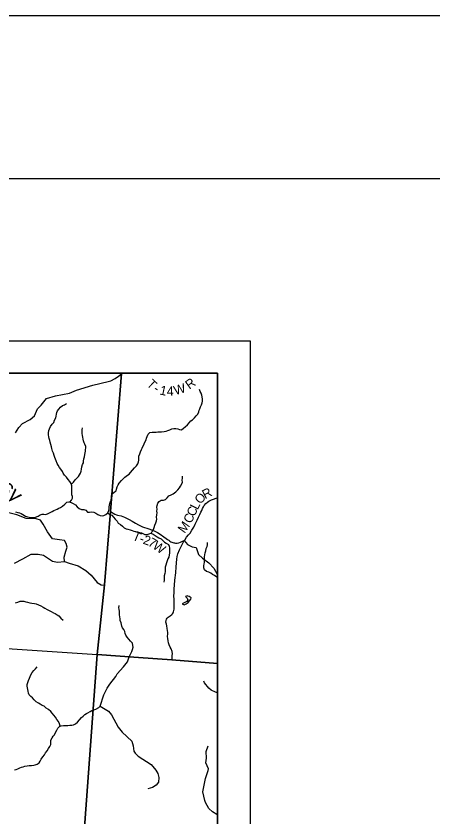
# Model space of a CAD drawing. Extents: x 0 to 42, y 0 to 22.
# Drawn here: x 8.279 to 9.563, y 19.536 to 22 of the extents above; entities that cross this region are included whole.
import ezdxf

# ---------------------------------------------------------------- set-up
doc = ezdxf.new("R2010")
doc.units = 0
for name, color, linetype in [('GM_X_Minor_Lake', 7, 'Continuous'), ('GM_X_Minor_River', 7, 'Continuous'), ('GM_X_Minor_River_Text', 7, 'Continuous'), ('GM_X_Township', 7, 'Continuous'), ('GM_X_Township_Road', 7, 'Continuous'), ('GM_X_Township_Road_Text', 7, 'Continuous'), ('SH_Border', 7, 'Continuous'), ('SH_Cut_Line', 7, 'Continuous'), ('SH_Data', 7, 'Continuous')]:
    doc.layers.add(name, color=color, linetype=linetype)

msp = doc.modelspace()

# ---------------------------------------------------------------- linework, layer by layer
at = {"layer": 'GM_X_Minor_Lake'}
for points in [[(8.8084, 20.2136), (8.8065, 20.2141), (8.8011, 20.2124), (8.8066, 20.2069), (8.8086, 20.202), (8.8047, 20.1969), (8.7905, 20.19)], [(8.7905, 20.19), (8.7969, 20.1862), (8.8034, 20.1893), (8.8098, 20.1942), (8.8138, 20.199), (8.8172, 20.2037), (8.8183, 20.2085), (8.8128, 20.2124), (8.8084, 20.2136)]]:
    msp.add_lwpolyline(points, dxfattribs=at)
at = {"layer": 'GM_X_Minor_River'}
for points in [[(8.5716, 20.5078), (8.5723, 20.5094), (8.5731, 20.5162), (8.5736, 20.521), (8.5747, 20.5274), (8.581, 20.5337), (8.5876, 20.5382), (8.5887, 20.543), (8.5912, 20.5502), (8.594, 20.5561), (8.597, 20.5612), (8.6036, 20.5694), (8.6099, 20.5756), (8.6148, 20.5798), (8.6223, 20.5855), (8.6274, 20.5895), (8.6318, 20.5943), (8.6376, 20.6011), (8.6444, 20.6085), (8.6503, 20.6144), (8.6542, 20.621), (8.6567, 20.6271), (8.6572, 20.6319), (8.6574, 20.6387), (8.6576, 20.6447), (8.66, 20.6516), (8.6627, 20.6578), (8.6657, 20.6645), (8.6672, 20.6692), (8.674, 20.6821), (8.6762, 20.6871), (8.6796, 20.6946), (8.6815, 20.7001), (8.6828, 20.7051), (8.6858, 20.7121), (8.6917, 20.7172), (8.6987, 20.718), (8.7055, 20.7188), (8.7104, 20.7188), (8.7157, 20.719), (8.7222, 20.7196), (8.7277, 20.7198), (8.7354, 20.7204), (8.7413, 20.7217), (8.7464, 20.7232), (8.7524, 20.7259), (8.7587, 20.7286), (8.7647, 20.7294), (8.7716, 20.7294), (8.7776, 20.7283), (8.7823, 20.7262), (8.789, 20.7256), (8.7945, 20.7302), (8.8005, 20.7348), (8.8075, 20.7414), (8.8122, 20.7475), (8.8179, 20.753), (8.823, 20.7566), (8.829, 20.7623), (8.8343, 20.7686), (8.8394, 20.7741), (8.8419, 20.7807), (8.8434, 20.7857), (8.8454, 20.7904), (8.8477, 20.7959), (8.8507, 20.8024), (8.8528, 20.8084), (8.8531, 20.8134), (8.8535, 20.8202), (8.8525, 20.8272), (8.8516, 20.8319), (8.8497, 20.8384), (8.8466, 20.8433), (8.8447, 20.8497)], [(8.4454, 20.5033), (8.45, 20.5087), (8.4534, 20.5149), (8.4527, 20.5202), (8.4514, 20.5252), (8.4514, 20.5433), (8.4511, 20.5488), (8.4509, 20.5536), (8.4496, 20.56), (8.4447, 20.5665), (8.4394, 20.5729), (8.4343, 20.5794), (8.4289, 20.5862), (8.4247, 20.5923), (8.4221, 20.5971), (8.4176, 20.6045), (8.4134, 20.6098), (8.4091, 20.6164), (8.4064, 20.6223), (8.4029, 20.6305), (8.4012, 20.6352), (8.3987, 20.6405), (8.3969, 20.6464), (8.3942, 20.6538), (8.3918, 20.6601), (8.3899, 20.6676), (8.3884, 20.6731), (8.3864, 20.6807), (8.3847, 20.6876), (8.3832, 20.6929), (8.3817, 20.6989), (8.3808, 20.7039), (8.3798, 20.7099), (8.3797, 20.7166), (8.3808, 20.7234), (8.3822, 20.7285), (8.3854, 20.7357), (8.3911, 20.7427), (8.3961, 20.7485), (8.398, 20.755), (8.402, 20.7622), (8.4029, 20.7675), (8.4039, 20.7733), (8.4052, 20.7786), (8.4075, 20.7841), (8.4108, 20.7894), (8.4163, 20.7957), (8.422, 20.8006), (8.4288, 20.8023), (8.4343, 20.8062)], [(8.45, 20.5582), (8.4559, 20.5642), (8.461, 20.5712), (8.4659, 20.5757), (8.472, 20.5816), (8.4743, 20.5871), (8.4775, 20.5924), (8.4798, 20.598), (8.4812, 20.6045), (8.4819, 20.6117), (8.4837, 20.6185), (8.4869, 20.6244), (8.4875, 20.6291), (8.4886, 20.6361), (8.49, 20.6429), (8.491, 20.6501), (8.4917, 20.6548), (8.4929, 20.6596), (8.4935, 20.6647), (8.4939, 20.6696), (8.4941, 20.6745), (8.4914, 20.681), (8.4894, 20.6859), (8.4871, 20.6922), (8.4858, 20.6971), (8.4847, 20.7032), (8.4841, 20.7081), (8.4832, 20.7146), (8.4827, 20.7195), (8.4827, 20.7256), (8.4835, 20.7322)], [(8.695, 20.4066), (8.6988, 20.4123), (8.7027, 20.4189), (8.7046, 20.4248), (8.7069, 20.4315), (8.7095, 20.4392), (8.7116, 20.4457), (8.7125, 20.4506), (8.7123, 20.4567), (8.7129, 20.4635), (8.7134, 20.47), (8.7132, 20.4749), (8.7134, 20.4813), (8.713, 20.4878), (8.7134, 20.4929), (8.7162, 20.4995), (8.7202, 20.5045), (8.7262, 20.5087), (8.7332, 20.5089), (8.7398, 20.5108), (8.7442, 20.5157), (8.7502, 20.5218), (8.757, 20.5254), (8.7633, 20.5285), (8.771, 20.5344), (8.7771, 20.5408), (8.7827, 20.5467), (8.7857, 20.5518), (8.7899, 20.5589), (8.7914, 20.5645), (8.7912, 20.5708), (8.7914, 20.5769), (8.7921, 20.5833)], [(8.278, 20.4735), (8.2848, 20.4714), (8.2903, 20.4695), (8.2952, 20.4676), (8.3003, 20.4648), (8.3081, 20.4602), (8.3143, 20.4581), (8.3198, 20.4565), (8.3262, 20.4558), (8.333, 20.4554), (8.3397, 20.4563), (8.3473, 20.4597), (8.3535, 20.4633), (8.3603, 20.4659), (8.3653, 20.4659), (8.3702, 20.4653), (8.3766, 20.4666), (8.3829, 20.4696), (8.3901, 20.4738), (8.396, 20.477), (8.4013, 20.4791), (8.406, 20.4811), (8.4113, 20.484), (8.416, 20.4866), (8.4223, 20.4907), (8.4291, 20.4966), (8.4358, 20.5023), (8.4422, 20.5043), (8.4494, 20.502), (8.4555, 20.4986), (8.4621, 20.4942), (8.4672, 20.4887), (8.4738, 20.4836), (8.4808, 20.4807), (8.4878, 20.4807), (8.4946, 20.4784), (8.4993, 20.4725), (8.5055, 20.4723), (8.5118, 20.4731), (8.5184, 20.4715)], [(8.5184, 20.4715), (8.5246, 20.4685), (8.5316, 20.4652), (8.5388, 20.4616), (8.5447, 20.4608), (8.5494, 20.4618), (8.5562, 20.4644), (8.5623, 20.4701), (8.5655, 20.4767), (8.5663, 20.4829), (8.5663, 20.4881), (8.5684, 20.4988), (8.5716, 20.5078)], [(8.5623, 20.4701), (8.568, 20.465)], [(8.568, 20.465), (8.5738, 20.4626), (8.5791, 20.4565), (8.5849, 20.4505), (8.5903, 20.444), (8.5942, 20.4382), (8.6007, 20.4337), (8.6071, 20.4284), (8.6123, 20.4242), (8.6187, 20.4204), (8.6236, 20.4197), (8.6312, 20.4172), (8.6369, 20.4152), (8.6416, 20.4137), (8.6465, 20.4124), (8.6536, 20.4116), (8.6594, 20.4099), (8.6661, 20.4079), (8.6714, 20.4052), (8.6761, 20.4037), (8.6829, 20.4034), (8.6891, 20.4053), (8.6941, 20.407), (8.7013, 20.404), (8.7077, 20.4), (8.7138, 20.3964), (8.7185, 20.3932), (8.7257, 20.3896), (8.736, 20.3794), (8.7418, 20.3766), (8.7483, 20.3728), (8.7511, 20.3668), (8.7515, 20.3609), (8.7515, 20.356), (8.7519, 20.351), (8.7517, 20.3455), (8.7508, 20.3408), (8.7493, 20.3338), (8.7469, 20.3288), (8.7446, 20.3226), (8.7429, 20.3163), (8.7408, 20.3091), (8.7384, 20.3023), (8.7382, 20.2956), (8.7382, 20.2896), (8.7375, 20.2835), (8.7358, 20.2761), (8.7352, 20.2695), (8.7353, 20.263), (8.7349, 20.256)], [(8.9, 20.2711), (8.8975, 20.272), (8.8906, 20.2769), (8.8844, 20.2805), (8.8789, 20.2843), (8.8726, 20.2873), (8.8662, 20.2897), (8.8599, 20.2941), (8.8575, 20.3001), (8.8573, 20.3068), (8.8582, 20.3124), (8.8595, 20.3172), (8.8597, 20.3231), (8.8597, 20.3295), (8.8598, 20.3344), (8.8602, 20.3405), (8.8621, 20.3468), (8.8636, 20.3528), (8.8651, 20.36), (8.8677, 20.3665), (8.8685, 20.3718), (8.869, 20.379)], [(8.2773, 20.1923), (8.2849, 20.1953), (8.2917, 20.1976), (8.2974, 20.1977), (8.3029, 20.1979), (8.3093, 20.1962), (8.3146, 20.1948), (8.3218, 20.1927), (8.3282, 20.1918), (8.3364, 20.1906), (8.3415, 20.1893), (8.3488, 20.187), (8.3555, 20.1837), (8.3628, 20.1793), (8.3685, 20.1761), (8.3747, 20.1727), (8.3813, 20.1692), (8.388, 20.1656), (8.3948, 20.162), (8.3997, 20.1597), (8.4057, 20.1555), (8.4108, 20.1525), (8.4174, 20.146), (8.4244, 20.1394)], [(8.6266, 20.0232), (8.6301, 20.0307), (8.6326, 20.0368), (8.6356, 20.0429), (8.6381, 20.0492), (8.6397, 20.0564), (8.6392, 20.0617), (8.6376, 20.0685), (8.6321, 20.0749), (8.6262, 20.0814), (8.6213, 20.0868), (8.6173, 20.0931), (8.6154, 20.0986), (8.6141, 20.1046), (8.6114, 20.1109), (8.6076, 20.1158), (8.6055, 20.1211), (8.6042, 20.1258), (8.6029, 20.131), (8.6004, 20.138), (8.5996, 20.1436), (8.5985, 20.1499), (8.5983, 20.1558), (8.5983, 20.1613), (8.5979, 20.1662), (8.5971, 20.173), (8.5961, 20.1779), (8.5971, 20.1846)], [(8.5186, 19.8633), (8.5248, 19.8655), (8.5339, 19.8704), (8.5383, 19.8748), (8.5496, 19.9095), (8.5603, 19.9298), (8.5679, 19.942), (8.5864, 19.9659), (8.5911, 19.9746), (8.6104, 19.9955), (8.6221, 20.0107), (8.6266, 20.0232)], [(8.4157, 19.8128), (8.4134, 19.8206), (8.41, 19.8272), (8.4051, 19.8339), (8.4011, 19.8403), (8.3953, 19.8468), (8.3908, 19.8529), (8.386, 19.8586), (8.3792, 19.8647), (8.3724, 19.8685), (8.366, 19.8742), (8.36, 19.877), (8.3532, 19.881), (8.3483, 19.8839), (8.3417, 19.8881), (8.3352, 19.8942), (8.3298, 19.8999), (8.325, 19.9046), (8.3203, 19.9096), (8.3181, 19.9149), (8.317, 19.9211), (8.3158, 19.9263), (8.3145, 19.9312), (8.314, 19.9361), (8.314, 19.941), (8.3155, 19.9475), (8.3176, 19.9532), (8.3205, 19.9605), (8.3228, 19.9655), (8.3249, 19.9713), (8.3294, 19.9782), (8.3344, 19.9844), (8.3393, 19.9891), (8.3443, 19.9954)], [(8.9, 19.9159), (8.8937, 19.9176), (8.8806, 19.9242), (8.8734, 19.9302), (8.86, 19.9469), (8.8579, 19.9513)], [(8.2746, 19.6781), (8.2795, 19.68), (8.2848, 19.682), (8.291, 19.6847), (8.2967, 19.6869), (8.3017, 19.6878), (8.3068, 19.6893), (8.3134, 19.691), (8.3196, 19.6918), (8.3266, 19.6921), (8.3337, 19.6933), (8.3386, 19.6942), (8.3448, 19.6961), (8.3503, 19.6998), (8.3536, 19.7053), (8.357, 19.7116), (8.3614, 19.719), (8.3667, 19.725), (8.3705, 19.7309), (8.3752, 19.7371), (8.3796, 19.7439), (8.3836, 19.7502), (8.3861, 19.7566), (8.3863, 19.7629), (8.3863, 19.7699), (8.3903, 19.7769), (8.3937, 19.7818), (8.3974, 19.7867), (8.4006, 19.7939), (8.4048, 19.8003), (8.4082, 19.8073), (8.413, 19.8117), (8.4179, 19.8138), (8.4253, 19.8147), (8.433, 19.815), (8.4393, 19.8154), (8.4446, 19.8156), (8.4508, 19.8163), (8.4558, 19.8174), (8.4628, 19.8206), (8.4685, 19.8257), (8.4743, 19.8324), (8.4808, 19.8395), (8.4856, 19.8437), (8.4911, 19.8492), (8.4958, 19.852), (8.5005, 19.8541), (8.5074, 19.8586), (8.5132, 19.8614), (8.5186, 19.8633)], [(8.5383, 19.8748), (8.5434, 19.8716), (8.5636, 19.8587), (8.5737, 19.8477), (8.5941, 19.8097), (8.6059, 19.7945), (8.6362, 19.7663), (8.6404, 19.7519), (8.6419, 19.7356), (8.6457, 19.7299), (8.6557, 19.7208), (8.6949, 19.6953), (8.7093, 19.6779), (8.7156, 19.6675), (8.7186, 19.6548), (8.7179, 19.6401), (8.7111, 19.6312), (8.699, 19.6242), (8.6855, 19.6196)], [(8.9, 19.5393), (8.8972, 19.5405), (8.8839, 19.5496), (8.8733, 19.5597), (8.8627, 19.578), (8.8602, 19.5837), (8.8549, 19.6104), (8.863, 19.6522), (8.8705, 19.6767), (8.8715, 19.6812), (8.8641, 19.7002), (8.8657, 19.7146), (8.8644, 19.7345), (8.8704, 19.752)]]:
    msp.add_lwpolyline(points, dxfattribs=at)
at = {"layer": 'GM_X_Township'}
msp.add_lwpolyline([(6.3062, 20.211), (6.4486, 20.1964), (6.4625, 20.1954), (6.5052, 20.1923), (6.9777, 20.151), (7.4661, 20.1144), (7.5116, 20.1083), (8.1585, 20.0585), (8.5294, 20.0335), (8.4853, 19.4313)], dxfattribs=at)
at = {"layer": 'GM_X_Township_Road'}
msp.add_line((8.604, 20.8984), (8.6056, 20.9), dxfattribs=at)
for points in [[(8.604, 20.9), (5.4466, 20.9), (5.4327, 20.7492), (5.4317, 20.7371), (5.4312, 20.7306), (5.4298, 20.7203), (5.4281, 20.716), (5.4083, 20.5211), (5.3882, 20.287), (5.7544, 20.2607), (6.2569, 20.215), (6.3062, 20.211), (6.4486, 20.1964), (6.4625, 20.1954), (6.5052, 20.1923), (6.9777, 20.151), (7.4661, 20.1144), (7.5116, 20.1083), (8.1585, 20.0585), (8.5294, 20.0335), (8.5516, 20.2479), (8.5706, 20.4739), (8.6039, 20.8987)], [(8.9, 20.0064), (8.9, 20.9), (8.604, 20.9), (8.6039, 20.8987), (8.5706, 20.4739), (8.5516, 20.2479), (8.5294, 20.0335), (8.6563, 20.0241), (8.7595, 20.0175)], [(8.9, 16.9577), (8.9, 20.0064), (8.7595, 20.0175), (8.6563, 20.0241), (8.5294, 20.0335), (8.4853, 19.4313), (8.4652, 19.1229), (8.4637, 19.1008), (8.4615, 19.0725), (8.4621, 19.064), (8.4621, 19.0593), (8.4614, 19.0466), (8.4612, 19.0401), (8.4609, 19.0269), (8.4213, 18.5141), (8.3877, 18.1065), (8.3223, 17.473), (8.3047, 17.0989), (8.2986, 17.0262), (8.2967, 17.0056), (8.3052, 17.0052), (8.669, 16.9761)]]:
    msp.add_lwpolyline(points, close=True, dxfattribs=at)
for points in [[(8.2775, 20.716), (8.2881, 20.7332), (8.2994, 20.7452), (8.3232, 20.7578), (8.3358, 20.7684), (8.3458, 20.7903), (8.3564, 20.8015), (8.373, 20.8221), (8.4008, 20.83), (8.4439, 20.8387), (8.4651, 20.8473), (8.5162, 20.8632), (8.5635, 20.8742), (8.5717, 20.8765), (8.5843, 20.8838), (8.5951, 20.8904), (8.604, 20.8984)], [(8.7658, 20.2213), (8.7662, 20.2353), (8.7685, 20.2612), (8.7687, 20.263), (8.7711, 20.2849), (8.7722, 20.3033), (8.7745, 20.327), (8.7756, 20.3355), (8.7775, 20.3435), (8.7826, 20.3562), (8.7974, 20.3843), (8.7997, 20.3881), (8.8046, 20.3953), (8.8102, 20.402), (8.8151, 20.4075), (8.8209, 20.4166), (8.8268, 20.4261), (8.8308, 20.435), (8.8369, 20.4474), (8.8408, 20.4564), (8.8449, 20.4653), (8.8484, 20.472), (8.851, 20.4776), (8.8539, 20.4831), (8.8565, 20.4886), (8.859, 20.4924), (8.8639, 20.4988), (8.8688, 20.5033), (8.8733, 20.5063), (8.881, 20.5102), (8.8872, 20.5124), (8.8954, 20.5147), (8.9, 20.5164)], [(8.5707, 20.4737), (8.5834, 20.4658), (8.5885, 20.4639), (8.5915, 20.4628), (8.6028, 20.4603), (8.6136, 20.4566), (8.6279, 20.4494), (8.6369, 20.4438), (8.647, 20.4379), (8.6567, 20.4333), (8.6685, 20.4267), (8.6878, 20.4207), (8.7044, 20.4149), (8.7144, 20.4098), (8.7233, 20.4043), (8.7347, 20.3962), (8.7419, 20.3907), (8.7461, 20.3877), (8.7499, 20.3853), (8.7532, 20.3829), (8.7563, 20.3808), (8.7593, 20.3794), (8.7623, 20.3782), (8.765, 20.3773), (8.7671, 20.3771), (8.7704, 20.3766), (8.7734, 20.3766), (8.7759, 20.377), (8.7804, 20.3778), (8.7862, 20.3798), (8.7916, 20.3828), (8.7974, 20.3843)], [(8.2742, 20.315), (8.3002, 20.328), (8.3263, 20.3427), (8.3478, 20.3427), (8.3642, 20.3393), (8.3914, 20.3212), (8.4067, 20.3184), (8.4282, 20.3201), (8.4271, 20.3338), (8.4326, 20.3514), (8.4366, 20.3644), (8.4338, 20.3757), (8.4282, 20.3845), (8.4127, 20.3866), (8.3916, 20.3901), (8.3761, 20.4112), (8.3634, 20.4352), (8.355, 20.4471), (8.3416, 20.4514), (8.3106, 20.4528), (8.2818, 20.4633), (8.2526, 20.4714)], [(8.7974, 20.3843), (8.8069, 20.3728), (8.8217, 20.3651), (8.834, 20.3633), (8.8374, 20.3544), (8.8407, 20.3416), (8.8539, 20.3301), (8.8731, 20.3164), (8.8883, 20.2994), (8.9, 20.2793)], [(8.4282, 20.3201), (8.4429, 20.3145), (8.4711, 20.3064), (8.4947, 20.2923), (8.5108, 20.2782), (8.5291, 20.255), (8.5415, 20.2483), (8.5517, 20.2476)], [(8.7597, 20.0172), (8.7597, 20.0236), (8.7603, 20.0301), (8.7606, 20.0358), (8.7599, 20.0425), (8.7568, 20.0513), (8.7541, 20.0567), (8.7513, 20.0632), (8.7491, 20.0695), (8.7474, 20.0757), (8.7465, 20.0829), (8.746, 20.0887), (8.7463, 20.0975), (8.7465, 20.1011), (8.7461, 20.1071), (8.7449, 20.1136), (8.7432, 20.1215), (8.7421, 20.1272), (8.741, 20.1337), (8.7411, 20.1379), (8.7423, 20.1422), (8.7448, 20.146), (8.7479, 20.1487), (8.7536, 20.1526), (8.7589, 20.1565), (8.7612, 20.1587), (8.7636, 20.1618), (8.7645, 20.1653), (8.7651, 20.1687), (8.7659, 20.173), (8.7662, 20.1853), (8.7663, 20.1989), (8.766, 20.2009), (8.7656, 20.2165), (8.7658, 20.2213)]]:
    msp.add_lwpolyline(points, dxfattribs=at)
at = {"layer": 'SH_Border'}
msp.add_lwpolyline([(1.5, 21.5), (33.5, 21.5), (33.5, 0.5), (1.5, 0.5)], close=True, dxfattribs=at)
at = {"layer": 'SH_Cut_Line'}
for points in [[(0, 0), (34, 0), (34, 22), (0, 22)], [(8.9, 20.0064), (8.9, 20.9), (8.604, 20.9), (8.6039, 20.8987), (8.5706, 20.4739), (8.5516, 20.2479), (8.5294, 20.0335), (8.6563, 20.0241), (8.7595, 20.0175)]]:
    msp.add_lwpolyline(points, close=True, dxfattribs=at)
for points in [[(8.1723, 15.4906), (8.2423, 16.3206), (8.2613, 16.5495), (8.2967, 17.0056), (8.2986, 17.0262), (8.3047, 17.0989), (8.3223, 17.473), (8.3877, 18.1065), (8.4213, 18.5141), (8.4609, 19.0269), (8.4612, 19.0401), (8.4614, 19.0466), (8.4621, 19.0593), (8.4621, 19.064), (8.4615, 19.0725), (8.4637, 19.1008), (8.4652, 19.1229), (8.4853, 19.4313), (8.5294, 20.0335), (8.5516, 20.2479), (8.5706, 20.4739), (8.6039, 20.8987), (8.604, 20.9), (2.1, 20.9)], [(8.9, 14.1), (8.9, 20.0064), (8.7595, 20.0175), (8.6563, 20.0241), (8.5294, 20.0335), (8.4853, 19.4313), (8.4652, 19.1229), (8.4637, 19.1008), (8.4615, 19.0725), (8.4621, 19.064), (8.4621, 19.0593), (8.4614, 19.0466), (8.4612, 19.0401), (8.4609, 19.0269), (8.4213, 18.5141), (8.3877, 18.1065), (8.3223, 17.473), (8.3047, 17.0989), (8.2986, 17.0262), (8.2967, 17.0056), (8.2613, 16.5495), (8.2423, 16.3206), (8.1723, 15.4906)]]:
    msp.add_lwpolyline(points, dxfattribs=at)
at = {"layer": 'SH_Data'}
for p, q in [((2, 21), (9, 21)), ((9, 21), (9, 14)), ((2.1, 20.9), (8.9, 20.9)), ((8.9, 20.9), (8.9, 14.1))]:
    msp.add_line(p, q, dxfattribs=at)

# ---------------------------------------------------------------- texts
at = {"layer": 'GM_X_Minor_River_Text'}
msp.add_text('Greasy', height=0.04734, rotation=315.0027, dxfattribs=at).set_placement((8.1288, 20.6422))
at = {"layer": 'GM_X_Township_Road_Text'}
for s, rotation, p in [('T', 315.6788, (8.6796, 20.8641)), ('W', 16.7453, (8.7698, 20.8321)), ('R', 35.5685, (8.8131, 20.8489)), ('-', 327.6483, (8.6998, 20.8452)), ('1', 347.9372, (8.7198, 20.8348)), ('4', 0.823, (8.7438, 20.8305)), ('O', 48.3196, (8.847, 20.4946)), ('R', 27.4186, (8.8614, 20.5116)), ('C', 64.7197, (8.8284, 20.4564)), ('L', 62.7373, (8.8383, 20.4772)), ('C', 65.6461, (8.8189, 20.4352)), ('M', 54.7525, (8.7982, 20.4049)), ('T', 337.3821, (8.6354, 20.3882)), ('2', 340.695, (8.668, 20.3756)), ('-', 341.6681, (8.6572, 20.3792)), ('7', 331.1144, (8.6833, 20.3704)), ('W', 324.6458, (8.6977, 20.3625))]:
    msp.add_text(s, height=0.0284, rotation=rotation, dxfattribs=at).set_placement(p)

doc.saveas('drawing.dxf')
